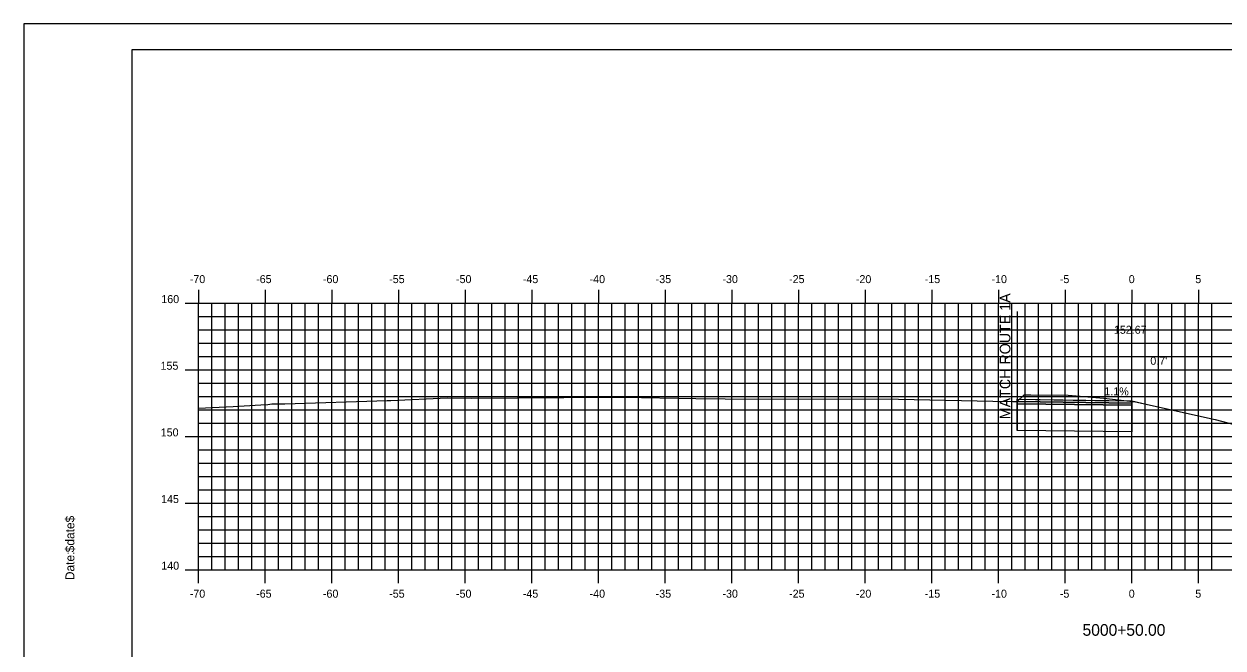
# Model space of a CAD drawing. Extents: x 850752 to 850923, y 365876 to 365986.
# Drawn here: x 850751.5 to 850841.5, y 365939 to 365985.8 of the extents above; entities that cross this region are included whole.
import ezdxf

# ---------------------------------------------------------------- set-up
doc = ezdxf.new("R2010")
doc.units = 0
for name, color, linetype in [('ANNOTATION', 7, 'Continuous'), ('BORDER', 7, 'Continuous'), ('D_Roadway_Centerline', 7, 'Continuous'), ('D_Roadway_Centerline_Text', 7, 'Continuous'), ('D_Roadway_Edge_TW', 7, 'Continuous'), ('D_Roadway_Pavement', 7, 'Continuous'), ('D_Roadway_SlopeLines', 7, 'Continuous'), ('D_Roadway_SubGrade', 7, 'Continuous'), ('D_Text_Standard', 7, 'Continuous'), ('H_V ANNOTATION', 7, 'Continuous'), ('MAJOR', 7, 'Continuous'), ('MINOR', 7, 'Continuous'), ('PLOT BOUNDARY', 7, 'Continuous'), ('S_Roadway_Centerline', 7, 'Continuous')]:
    doc.layers.add(name, color=color, linetype=linetype)

msp = doc.modelspace()

# ---------------------------------------------------------------- linework, layer by layer
at = {"layer": 'BORDER'}
msp.add_lwpolyline([(850759.629, 365878.833), (850919.629, 365878.833), (850919.629, 365983.833), (850759.629, 365983.833)], close=True, dxfattribs=at)
at = {"layer": 'D_Roadway_Centerline'}
msp.add_lwpolyline([(850826.019, 365957.615), (850828.778, 365957.573), (850830.225, 365957.555), (850831.855, 365957.532), (850834.63, 365957.501), (850834.915, 365957.429), (850835.368, 365957.315)], dxfattribs=at)
at = {"layer": 'D_Roadway_Edge_TW'}
msp.add_lwpolyline([(850826.019, 365957.615), (850834.63, 365957.501), (850834.63, 365957.334), (850826.019, 365957.449)], close=True, dxfattribs=at)
at = {"layer": 'D_Roadway_Pavement'}
msp.add_lwpolyline([(850826.019, 365957.449), (850834.63, 365957.334), (850834.63, 365957.167), (850826.019, 365957.282)], close=True, dxfattribs=at)
msp.add_lwpolyline([(850834.63, 365957.334), (850834.63, 365957.167)], dxfattribs=at)
msp.add_lwpolyline([(850834.63, 365957.334), (850834.63, 365957.167)], dxfattribs=at)
at = {"layer": 'D_Roadway_SlopeLines'}
msp.add_lwpolyline([(850834.63, 365957.501), (850835.368, 365957.315)], dxfattribs=at)
msp.add_lwpolyline([(850834.63, 365957.501), (850835.368, 365957.315)], dxfattribs=at)
at = {"layer": 'D_Roadway_SubGrade'}
msp.add_line((850826.019, 365964.199), (850826.019, 365955.282), dxfattribs=at)
msp.add_lwpolyline([(850826.019, 365957.282), (850834.63, 365957.167), (850834.63, 365955.167), (850826.019, 365955.282)], close=True, dxfattribs=at)
at = {"layer": 'MAJOR'}
for p, q in [((850764.629, 365965.835), (850764.629, 365964.833)), ((850769.629, 365965.835), (850769.629, 365964.833)), ((850774.629, 365965.835), (850774.629, 365964.833)), ((850779.629, 365965.835), (850779.629, 365964.833)), ((850784.629, 365965.835), (850784.629, 365964.833)), ((850789.629, 365965.835), (850789.629, 365964.833)), ((850794.629, 365965.835), (850794.629, 365964.833)), ((850799.629, 365965.835), (850799.629, 365964.833)), ((850804.629, 365965.835), (850804.629, 365964.833)), ((850809.629, 365965.835), (850809.629, 365964.833)), ((850814.629, 365965.835), (850814.629, 365964.833)), ((850819.629, 365965.835), (850819.629, 365964.833)), ((850824.629, 365965.835), (850824.629, 365964.833)), ((850829.629, 365965.835), (850829.629, 365964.833)), ((850834.629, 365965.835), (850834.629, 365964.833)), ((850839.629, 365965.835), (850839.629, 365964.833)), ((850763.627, 365964.833), (850764.629, 365964.833)), ((850764.629, 365964.833), (850904.629, 365964.833)), ((850764.629, 365944.833), (850764.629, 365964.833)), ((850764.629, 365944.833), (850764.629, 365964.833)), ((850764.629, 365964.833), (850904.629, 365964.833)), ((850769.629, 365944.833), (850769.629, 365964.833)), ((850774.629, 365944.833), (850774.629, 365964.833)), ((850779.629, 365944.833), (850779.629, 365964.833)), ((850784.629, 365944.833), (850784.629, 365964.833)), ((850789.629, 365944.833), (850789.629, 365964.833)), ((850794.629, 365944.833), (850794.629, 365964.833)), ((850799.629, 365944.833), (850799.629, 365964.833)), ((850804.629, 365944.833), (850804.629, 365964.833)), ((850809.629, 365944.833), (850809.629, 365964.833)), ((850814.629, 365944.833), (850814.629, 365964.833)), ((850819.629, 365944.833), (850819.629, 365964.833)), ((850824.629, 365944.833), (850824.629, 365964.833)), ((850829.629, 365944.833), (850829.629, 365964.833)), ((850834.629, 365944.833), (850834.629, 365964.833)), ((850839.629, 365944.833), (850839.629, 365964.833)), ((850763.627, 365959.833), (850764.629, 365959.833)), ((850764.629, 365959.833), (850904.629, 365959.833)), ((850763.627, 365954.833), (850764.629, 365954.833)), ((850764.629, 365954.833), (850904.629, 365954.833)), ((850763.627, 365949.833), (850764.629, 365949.833)), ((850764.629, 365949.833), (850904.629, 365949.833)), ((850763.627, 365944.833), (850764.629, 365944.833)), ((850764.629, 365944.833), (850904.629, 365944.833)), ((850764.629, 365944.833), (850904.629, 365944.833)), ((850764.629, 365943.831), (850764.629, 365944.833)), ((850769.629, 365943.831), (850769.629, 365944.833)), ((850774.629, 365943.831), (850774.629, 365944.833)), ((850779.629, 365943.831), (850779.629, 365944.833)), ((850784.629, 365943.831), (850784.629, 365944.833)), ((850789.629, 365943.831), (850789.629, 365944.833)), ((850794.629, 365943.831), (850794.629, 365944.833)), ((850799.629, 365943.831), (850799.629, 365944.833)), ((850804.629, 365943.831), (850804.629, 365944.833)), ((850809.629, 365943.831), (850809.629, 365944.833)), ((850814.629, 365943.831), (850814.629, 365944.833)), ((850819.629, 365943.831), (850819.629, 365944.833)), ((850824.629, 365943.831), (850824.629, 365944.833)), ((850829.629, 365943.831), (850829.629, 365944.833)), ((850834.629, 365943.831), (850834.629, 365944.833)), ((850839.629, 365943.831), (850839.629, 365944.833))]:
    msp.add_line(p, q, dxfattribs=at)
at = {"layer": 'MINOR'}
for p, q in [((850765.629, 365944.833), (850765.629, 365964.833)), ((850766.629, 365944.833), (850766.629, 365964.833)), ((850767.629, 365944.833), (850767.629, 365964.833)), ((850768.629, 365944.833), (850768.629, 365964.833)), ((850770.629, 365944.833), (850770.629, 365964.833)), ((850771.629, 365944.833), (850771.629, 365964.833)), ((850772.629, 365944.833), (850772.629, 365964.833)), ((850773.629, 365944.833), (850773.629, 365964.833)), ((850775.629, 365944.833), (850775.629, 365964.833)), ((850776.629, 365944.833), (850776.629, 365964.833)), ((850777.629, 365944.833), (850777.629, 365964.833)), ((850778.629, 365944.833), (850778.629, 365964.833)), ((850780.629, 365944.833), (850780.629, 365964.833)), ((850781.629, 365944.833), (850781.629, 365964.833)), ((850782.629, 365944.833), (850782.629, 365964.833)), ((850783.629, 365944.833), (850783.629, 365964.833)), ((850785.629, 365944.833), (850785.629, 365964.833)), ((850786.629, 365944.833), (850786.629, 365964.833)), ((850787.629, 365944.833), (850787.629, 365964.833)), ((850788.629, 365944.833), (850788.629, 365964.833)), ((850790.629, 365944.833), (850790.629, 365964.833)), ((850791.629, 365944.833), (850791.629, 365964.833)), ((850792.629, 365944.833), (850792.629, 365964.833)), ((850793.629, 365944.833), (850793.629, 365964.833)), ((850795.629, 365944.833), (850795.629, 365964.833)), ((850796.629, 365944.833), (850796.629, 365964.833)), ((850797.629, 365944.833), (850797.629, 365964.833)), ((850798.629, 365944.833), (850798.629, 365964.833)), ((850800.629, 365944.833), (850800.629, 365964.833)), ((850801.629, 365944.833), (850801.629, 365964.833)), ((850802.629, 365944.833), (850802.629, 365964.833)), ((850803.629, 365944.833), (850803.629, 365964.833)), ((850805.629, 365944.833), (850805.629, 365964.833)), ((850806.629, 365944.833), (850806.629, 365964.833)), ((850807.629, 365944.833), (850807.629, 365964.833)), ((850808.629, 365944.833), (850808.629, 365964.833)), ((850810.629, 365944.833), (850810.629, 365964.833)), ((850811.629, 365944.833), (850811.629, 365964.833)), ((850812.629, 365944.833), (850812.629, 365964.833)), ((850813.629, 365944.833), (850813.629, 365964.833)), ((850815.629, 365944.833), (850815.629, 365964.833)), ((850816.629, 365944.833), (850816.629, 365964.833)), ((850817.629, 365944.833), (850817.629, 365964.833)), ((850818.629, 365944.833), (850818.629, 365964.833)), ((850820.629, 365944.833), (850820.629, 365964.833)), ((850821.629, 365944.833), (850821.629, 365964.833)), ((850822.629, 365944.833), (850822.629, 365964.833)), ((850823.629, 365944.833), (850823.629, 365964.833)), ((850825.629, 365944.833), (850825.629, 365964.833)), ((850826.629, 365944.833), (850826.629, 365964.833)), ((850827.629, 365944.833), (850827.629, 365964.833)), ((850828.629, 365944.833), (850828.629, 365964.833)), ((850830.629, 365944.833), (850830.629, 365964.833)), ((850831.629, 365944.833), (850831.629, 365964.833)), ((850832.629, 365944.833), (850832.629, 365964.833)), ((850833.629, 365944.833), (850833.629, 365964.833)), ((850835.629, 365944.833), (850835.629, 365964.833)), ((850836.629, 365944.833), (850836.629, 365964.833)), ((850837.629, 365944.833), (850837.629, 365964.833)), ((850838.629, 365944.833), (850838.629, 365964.833)), ((850840.629, 365944.833), (850840.629, 365964.833)), ((850764.629, 365963.833), (850904.629, 365963.833)), ((850764.629, 365963.833), (850765.631, 365963.833)), ((850764.629, 365962.833), (850904.629, 365962.833)), ((850764.629, 365962.833), (850765.631, 365962.833)), ((850764.629, 365961.833), (850904.629, 365961.833)), ((850764.629, 365961.833), (850765.631, 365961.833)), ((850764.629, 365960.833), (850904.629, 365960.833)), ((850764.629, 365960.833), (850765.631, 365960.833)), ((850764.629, 365958.833), (850904.629, 365958.833)), ((850764.629, 365958.833), (850765.631, 365958.833)), ((850764.629, 365957.833), (850904.629, 365957.833)), ((850764.629, 365957.833), (850765.631, 365957.833)), ((850764.629, 365956.833), (850904.629, 365956.833)), ((850764.629, 365956.833), (850765.631, 365956.833)), ((850764.629, 365955.833), (850904.629, 365955.833)), ((850764.629, 365955.833), (850765.631, 365955.833)), ((850764.629, 365953.833), (850904.629, 365953.833)), ((850764.629, 365953.833), (850765.631, 365953.833)), ((850764.629, 365952.833), (850904.629, 365952.833)), ((850764.629, 365952.833), (850765.631, 365952.833)), ((850764.629, 365951.833), (850904.629, 365951.833)), ((850764.629, 365951.833), (850765.631, 365951.833)), ((850764.629, 365950.833), (850904.629, 365950.833)), ((850764.629, 365950.833), (850765.631, 365950.833)), ((850764.629, 365948.833), (850904.629, 365948.833)), ((850764.629, 365948.833), (850765.631, 365948.833)), ((850764.629, 365947.833), (850904.629, 365947.833)), ((850764.629, 365947.833), (850765.631, 365947.833)), ((850764.629, 365946.833), (850904.629, 365946.833)), ((850764.629, 365946.833), (850765.631, 365946.833)), ((850764.629, 365945.833), (850904.629, 365945.833)), ((850764.629, 365945.833), (850765.631, 365945.833))]:
    msp.add_line(p, q, dxfattribs=at)
at = {"layer": 'PLOT BOUNDARY'}
msp.add_lwpolyline([(850751.536, 365875.774), (850921.536, 365875.774), (850921.536, 365985.774), (850751.536, 365985.774)], close=True, dxfattribs=at)
at = {"layer": 'S_Roadway_Centerline'}
msp.add_lwpolyline([(850764.629, 365956.957), (850767.236, 365957.076), (850769.311, 365957.199), (850769.827, 365957.236), (850770.116, 365957.28), (850771.101, 365957.275), (850778.769, 365957.522), (850779.044, 365957.532), (850783.268, 365957.717), (850785.105, 365957.713), (850795.463, 365957.78), (850795.758, 365957.782), (850795.794, 365957.782), (850796.489, 365957.769), (850801.927, 365957.666), (850804.114, 365957.649), (850817.111, 365957.621), (850824.204, 365957.486), (850825.69, 365957.455), (850826.025, 365957.441), (850826.528, 365957.926), (850826.553, 365957.95), (850827.036, 365957.946), (850829.849, 365957.931), (850832.511, 365957.702), (850834.895, 365957.421), (850840.868, 365956.102), (850843.133, 365955.511)], dxfattribs=at)

# ---------------------------------------------------------------- texts
at = {"layer": 'ANNOTATION'}
for s, height, rotation, p in [('MATCH ROUTE 1A', 0.8, 90, (850825.513, 365956.117)), ('1.1%', 0.6, 359.35422, (850832.558, 365957.924))]:
    msp.add_text(s, height=height, rotation=rotation, dxfattribs=at).set_placement(p)
at = {"layer": 'BORDER'}
for s, p in [('$date$', (850755.314, 365946.138)), ('Date:', (850755.314, 365944.05))]:
    msp.add_text(s, height=0.6696, rotation=90, dxfattribs=at).set_placement(p)
at = {"layer": 'D_Roadway_Centerline_Text'}
msp.add_text('152.67', height=0.6, dxfattribs=at).set_placement((850833.275, 365962.533))
at = {"layer": 'D_Text_Standard'}
msp.add_text("0.7'", height=0.6, dxfattribs=at).set_placement((850836.007, 365960.207))
at = {"layer": 'H_V ANNOTATION'}
for s, height, p in [('-70', 0.6, (850763.97, 365966.333)), ('-65', 0.6, (850768.946, 365966.333)), ('-60', 0.6, (850773.954, 365966.333)), ('-55', 0.6, (850778.925, 365966.333)), ('-50', 0.6, (850783.933, 365966.333)), ('-45', 0.6, (850788.946, 365966.333)), ('-40', 0.6, (850793.954, 365966.333)), ('-35', 0.6, (850798.909, 365966.333)), ('-30', 0.6, (850803.917, 365966.333)), ('-25', 0.6, (850808.914, 365966.333)), ('-20', 0.6, (850813.922, 365966.333)), ('-15', 0.6, (850819.086, 365966.333)), ('-10', 0.6, (850824.094, 365966.333)), ('-5', 0.6, (850829.219, 365966.333)), ('0', 0.6, (850834.388, 365966.333)), ('5', 0.6, (850839.38, 365966.333)), ('160', 0.6, (850761.834, 365964.833)), ('155', 0.6, (850761.775, 365959.833)), ('150', 0.6, (850761.791, 365954.833)), ('145', 0.6, (850761.818, 365949.833)), ('140', 0.6, (850761.834, 365944.833)), ('-70', 0.6, (850763.97, 365942.733)), ('-65', 0.6, (850768.946, 365942.733)), ('-60', 0.6, (850773.954, 365942.733)), ('-55', 0.6, (850778.925, 365942.733)), ('-50', 0.6, (850783.933, 365942.733)), ('-45', 0.6, (850788.946, 365942.733)), ('-40', 0.6, (850793.954, 365942.733)), ('-35', 0.6, (850798.909, 365942.733)), ('-30', 0.6, (850803.917, 365942.733)), ('-25', 0.6, (850808.914, 365942.733)), ('-20', 0.6, (850813.922, 365942.733)), ('-15', 0.6, (850819.086, 365942.733)), ('-10', 0.6, (850824.094, 365942.733)), ('-5', 0.6, (850829.219, 365942.733)), ('0', 0.6, (850834.388, 365942.733)), ('5', 0.6, (850839.38, 365942.733)), ('5000+50.00', 0.875, (850830.922, 365939.876))]:
    msp.add_text(s, height=height, dxfattribs=at).set_placement(p)
at = {"layer": 'MAJOR'}
msp.add_text('-', height=0.006, dxfattribs=at).set_placement((850764.624, 365944.833))

doc.saveas('drawing.dxf')
